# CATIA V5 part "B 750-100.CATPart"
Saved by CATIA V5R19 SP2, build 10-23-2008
Part number: B 750-100
Bounding box of the stored display mesh (mm): x -22.494 to 22.494, y -22.494 to 22.494, z 0 to 285
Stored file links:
  C:\Users\Bora\Desktop\3D Katı model\B serisi\B 750\B 750-100.CATPart
  C:\Program Files\Dassault Systemes\B19\intel_a\reffiles\standard\MetricThickPitch.txt
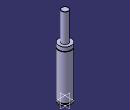
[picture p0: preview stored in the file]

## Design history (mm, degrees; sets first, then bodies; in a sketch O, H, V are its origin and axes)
Body1 (main body)
  Sketch1 on yz-plane, origin (0, 0, 0), H (0, 1, 0), V (0, 0, 1)
    point P3 (12, 284)
    point P5 (12, 284)
    point P7 (22.5, 169.5)
    point P8 (22.5, 167.5)
    point P12 (22.5, 167.5)
    point P13 (22.5, 169.5)
    line L1 (22.5, 0) -> (22.5, 4)
    line L2 (12, 284) -> (12, 183)
    arc A1 centre (11, 284) radius 1 from (12, 284) to (11, 285) ccw
    arc A2 centre (22.5, 168.5) radius 1 from (22.5, 169.5) to (22.5, 167.5) ccw
    line L3 (20, 7.5) -> (20, 4)
    line L4 (22.5, 7.5) -> (22.5, 167.5)
    line L5 (22.5, 169.5) -> (22.5, 183)
    line L6 (11, 285) -> (0, 285)
    point P15 (0, 285)
    line L7 (12, 183) -> (22.5, 183)
    line L8 (0, 0) -> (22.5, 0)
    line L9 (20, 7.5) -> (22.5, 7.5)
    line L10 (20, 4) -> (22.5, 4)
    coincidence: P15 V, P3 P5, P7 P13, P8 P12
    tangency: L6 A1
    horizontal: L7 H, L8 H, L9 H, L10 H
  Shaft1: profile Sketch1, axis Sketch1.V, angle 360
  Sketch2 on face of Shaft1 from Sketch1.L8, origin (0, 0, 0), H (1, 0, 0), V (0, -1, 0)
    point P1 (10, 0)
    distance P1 V = 10
  Hole1: placed by Sketch2, at (10, 0, 0) direction (0, 0, 1), diameter 6.647, depth 13, threaded "M8", thread diameter 8, thread depth 13, pitch 1.25
  CircPattern1: of Hole1, instances 2, angular step 180, axis from xy-plane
